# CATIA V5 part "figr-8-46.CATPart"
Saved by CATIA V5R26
Part number: Part1
Bounding box of the stored display mesh (mm): x -46.99 to 46.99, y -111.421 to 111.421, z 0 to 30
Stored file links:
  D:\_Deepak\CATIA\CATIA V5-6R2016_Deepak\Resources\Part files\Partfiles\c08_catia_v5_6r2016_prt\figr-8-46.CATPart
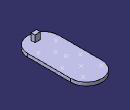
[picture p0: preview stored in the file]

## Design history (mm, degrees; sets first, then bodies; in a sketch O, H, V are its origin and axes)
Set1
  Point1: type OnPlane, Support end face of Pad1, H -29.651, V 16.503, Direction (1, 0, 0)
  Point2: type OnPlane, Support end face of Pad1, H 32.527, V 24.633, Direction (1, 0, 0)
  Point3: type OnPlane, Support end face of Pad1, H -0.958, V 47.624, Direction (1, 0, 0)
  Point4: type OnPlane, Support end face of Pad1, H -32.979, V 77.546, Direction (1, 0, 0)
  Point5: type OnPlane, Support end face of Pad1, H -4.198, V -0.555, Direction (1, 0, 0)
  Point6: type OnPlane, Support end face of Pad1, H 24.642, V 78.69, Direction (1, 0, 0)
  Point7: type OnPlane, Support end face of Pad1, H 1.401, V -27.141, Direction (1, 0, 0)
  Point8: type OnPlane, Support end face of Pad1, H -28.672, V -54.785, Direction (1, 0, 0)
  Point9: type OnPlane, Support end face of Pad1, H 29.834, V -50.327, Direction (1, 0, 0)
Body1 (main body)
  Sketch1 on xy-plane, origin (0, 0, 0), H (1, 0, 0), V (0, 1, 0)
    construction line L1 (-46.9897, 64.4313) -> (46.9897, 64.4313)
    line L2 (46.9897, 64.4313) -> (46.9897, -64.4313)
    construction line L3 (46.9897, -64.4313) -> (-46.9897, -64.4313)
    line L4 (-46.9897, -64.4313) -> (-46.9897, 64.4313)
    axis line L5 (46.9897, -64.4313) -> (-46.9897, 64.4313)
    arc A1 centre (0, 64.4313) radius 46.9897 from (-46.9897, 64.4313) to (46.9897, 64.4313) cw
    arc A2 centre (0, -64.4313) radius 46.9897 from (-46.9897, -64.4313) to (46.9897, -64.4313) ccw
    point P7 (0, -111.4211)
    length L3 = 93.9795
    length L2 = 128.8627
    horizontal: L1 H, L3 H
    vertical: L2 V, L4 V
    midpoint: O L5
    tangency: A1 L2, A2 L4
    coincidence: A2 P7, P7 V
  Pad1: profile Sketch1, direction (0, 0, 1), length 10
  Sketch2 on face of Pad1, origin (0, 0, 10), H (1, 0, 0), V (0, 1, 0)
    line L1 (-8.4317, -82.0722) -> (8.3047, -82.0722)
    line L2 (8.3047, -82.0722) -> (8.3047, -93.8638)
    line L3 (8.3047, -93.8638) -> (-8.4317, -93.8638)
    line L4 (-8.4317, -93.8638) -> (-8.4317, -82.0722)
    horizontal: L1 H, L3 H
    vertical: L2 V, L4 V
  Pad2: profile Sketch2, direction (0, 0, 1), length 20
